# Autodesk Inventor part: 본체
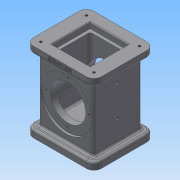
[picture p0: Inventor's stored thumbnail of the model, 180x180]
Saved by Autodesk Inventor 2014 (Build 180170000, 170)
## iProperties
Created: 2017-08
Part Number: 본체
Material: Generic
Document SubType Name: Modeling
Designer: oa51
Density: 1 g/cm^3
Appearance: Default
Author: oa51
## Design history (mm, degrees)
sketch "스케치1"
  geometry: L1 (-46, -41)-(46, -41); L2 (46, -41)-(46, 41); L3 (46, 41)-(-46, 41); L4 (-46, 41)-(-46, -41); L5 (-46, -41)-(46, 41); L6 (46, -41)-(-46, 41); 1 further point
  constraints: 12 end point, 2 midpoint, 2 parallel, 1 horizontal, 1 perpendicular
  dimensions: "d0" = 92 distance of L2.end L3.end; "d1" = 82 distance of L1.end L2.end
extrude "돌출1" new body sketch "스케치1" distance "d2" = 10; taper "d3" = 0 deg
node "작업 평면1"
sketch "스케치2"
  geometry: L1 (-37, -33)-(37, -33); L2 (37, -33)-(37, 33); L3 (37, 33)-(-37, 33); L4 (-37, 33)-(-37, -33); L5 (-37, -33)-(37, 33); L6 (37, -33)-(-37, 33); 1 further point
  constraints: 12 end point, 2 midpoint, 2 parallel, 1 horizontal, 1 perpendicular
  dimensions: "d5" = 74 distance of L2.end L3.end; "d6" = 66 distance of L1.end L2.end
extrude "돌출2" join sketch "스케치2" stored distance "d7" = 10; taper "d8" = 0 deg
sketch "스케치4"
  geometry: L1 (-33, 54)-(33, 54); L2 (-41, 0)-(41, 0) reference; L3 (-33, 98)-(33, 98) reference; L4 (-33, 10)-(-33, 98) reference; L5 (33, 10)-(-33, 10) reference; L6 (33, 10)-(33, 98) reference; L7 (-33, 54)-(-33, 89); L8 (-33, 89)-(-30, 89); L9 (-30, 89)-(-30, 78); L10 (-30, 78)-(30, 78); L11 (30, 78)-(30, 89); L12 (30, 89)-(33, 89); L13 (33, 54)-(33, 89); 1 further point
  constraints: 16 end point, 3 perpendicular, 2 midpoint, 2 parallel, 2 point on line, 1 collinear, 1 horizontal
  dimensions: "d12" = 108 diameter of L2 L1 (derived); "d13" = 3 distance of L7.end L8.end; "d14" = 3 distance of L11.end L12.end (= d13); "d15" = 70 diameter of L8 L1; "d16" = 70 diameter of L12 L1; "d17" = 48 diameter of L10 L1
revolve "회전1" sketch "스케치4" stored, may be unused: angle "d18" = 90 deg
sketch "스케치5"
  geometry: L1 (24, 19)-(68, 19); L2 (68, 19)-(68, 63); L3 (68, 63)-(24, 63); L4 (24, 63)-(24, 19); L5 (24, 19)-(68, 63); L6 (68, 19)-(24, 63); 1 further point
  constraints: 12 end point, 2 midpoint, 2 parallel, 1 horizontal, 1 perpendicular
  dimensions: "d19" = 44 distance of L2.end L3.end; "d20" = 44 distance of L1.end L2.end (= d19)
extrude "돌출3" cut sketch "스케치5" distance "d21" = 82; taper "d22" = 0 deg
sketch "스케치6"
  geometry: L1 (68, 63)-(68, 19) reference; L2 (68, 19)-(24, 19) reference; L3 (24, 19)-(24, 63) reference; L4 (24, 63)-(68, 63) reference; L5 (20, 15)-(72, 15); L6 (72, 15)-(72, 67); L7 (72, 67)-(20, 67); L8 (20, 67)-(20, 15); L9 (20, 15)-(72, 67); L10 (72, 15)-(20, 67); 1 further point
  constraints: 12 end point, 2 midpoint, 2 parallel, 1 horizontal, 1 perpendicular
  dimensions: "d23" = 52 distance of L6.end L7.end; "d24" = 52 distance of L5.end L6.end
extrude "돌출4" cut sketch "스케치6" distance "d25" = 8; taper "d26" = 0 deg
sketch "스케치7"
  geometry: L1 (-24, -24)-(24, -24); L2 (24, -24)-(24, 24); L3 (24, 24)-(-24, 24); L4 (-24, 24)-(-24, -24); L5 (-24, -24)-(24, 24); L6 (24, -24)-(-24, 24); 1 further point
  constraints: 12 end point, 2 midpoint, 2 parallel, 1 horizontal, 1 perpendicular
  dimensions: "d27" = 48 distance of L2.end L3.end; "d28" = 48 distance of L1.end L2.end (= d27)
extrude "돌출5" cut sketch "스케치7" distance "d29" = 16; taper "d30" = 0 deg
sketch "스케치8"
  geometry: L1 (0, 82)-(0, 0) reference; L2 (46, 41)-(36.381, 41); 4 further points
  constraints: 2 end point, 2 symmetric about line, 1 horizontal alignment, 1 perpendicular
  dimensions: "d31" = 72 distance of point (10, 72) point (82, 72); "d32" = 10 horizontal distance of L1.start point (10, 72); "d33" = 10 horizontal distance of L1.start point (10, 72)
hole "구멍1" sketch "스케치8" at (10, 72), (82, 72), (10, 10), (82, 10) diameter "d34" = 3.242; stored, may be unused: countersink angle "d38" = 90 deg, drill point angle "d40" = 118 deg; dims "d35" = 4, "d36" = 4, "d37" = 2, "d39" = 6
node "작업 평면2"
sketch "스케치9" dims "d41" = 58
  geometry: C1 r 35 at (0, 0) reference; C2 r 24 at (0, 0) reference; 6 further points
  constraints: 1 coincident, 1 vertical alignment, 7 other
  dimensions: "d44" = 360 deg dimension on C1.centre point (0, 29) (derived)
hole "구멍2" sketch "스케치9" at (0, 29), (-29, 0), (0, -29), (29, 0) diameter "d46" = 3.242; stored, may be unused: countersink angle "d50" = 90 deg, drill point angle "d52" = 118 deg; dims "d47" = 4, "d48" = 4, "d49" = 2, "d51" = 6
sketch "스케치10"
  geometry: L1 (-98, -8)-(-98, 74) reference; L2 (10, -8)-(10, 74) reference; 4 further points
  constraints: 2 horizontal alignment, 1 midpoint
  dimensions: "d53" = 38 distance from line of L2 point (-28, 33); "d54" = 42 distance of point (-70, 33) point (-28, 33)
hole "구멍3" sketch "스케치10" at (-70, 33), (-28, 33) diameter "d55" = 4.134; stored, may be unused: countersink angle "d59" = 90 deg, drill point angle "d61" = 118 deg; dims "d56" = 29, "d57" = 4, "d58" = 2, "d60" = 29
fillet "모깎기1" dims "d63" = 3
fillet "모깎기2" dims "d64" = 10
fillet "모깎기3" dims "d65" = 3
chamfer "모따기1" distance "d66" = 1; stored, may be unused: second distance "d67" = 2, angle "d68" = 45 deg
fillet "모깎기4" dims "d69" = 3
fillet "모깎기6" dims "d71" = 3
fillet "모깎기7" dims "d72" = 3
fillet "모깎기8" dims "d73" = 3
fillet "모깎기9" dims "d74" = 3
node "작업 평면3"
sketch "스케치11"
  geometry: L1 (0, 0)-(0, -7) reference; L2 (10, 0)-(82, 0) reference; 2 further points
  constraints: 1 other
  dimensions: "d75" = 46 distance from line of point (46, -4) L1; "d76" = 4 distance from line of L2 point (46, -4)
feature "엠보싱1" sketch "스케치11" dims "d0" = 92, "d1" = 82, "d77" = 0.5, "d78" = 0
node "솔리드1"
mirror "대칭1"
mirror "대칭2"
mirror "대칭3"
node "투영된 루프2"
other parameters: "d4" = -54, "d62" = 60.75
